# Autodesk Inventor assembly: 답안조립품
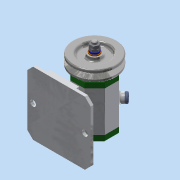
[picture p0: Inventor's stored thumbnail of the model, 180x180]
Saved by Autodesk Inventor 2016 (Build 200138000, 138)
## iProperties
Created: 2018-06
Part Number: 답안조립품
Material: 일반
Document SubType Name: Assembly
Designer: 605-07
Author: 605-07
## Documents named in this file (16)
- C:\Users\605-07\Desktop\480608V1002\답안조립품.iam
- C:\Users\605-07\Desktop\480608V1002\V벨트풀리.ipt
- C:\Users\605-07\Desktop\480608V1002\고무캡.ipt
- C:\Users\605-07\Desktop\480608V1002\너트 M8.ipt
- 너트 M8.ipt
- C:\Users\605-07\Desktop\480608V1002\뒤커버.ipt
- C:\Users\605-07\Desktop\480608V1002\베어링 15x32x9.ipt
- C:\Users\605-07\Desktop\480608V1002\본체.ipt
- C:\Users\605-07\Desktop\480608V1002\볼트 M4x12.ipt
- C:\Users\605-07\Desktop\480608V1002\스프링와셔 8.ipt
- C:\Users\605-07\Desktop\480608V1002\앞커버.ipt
- C:\Users\605-07\Desktop\480608V1002\오일 실 15 25 7.ipt
- C:\Users\605-07\Desktop\480608V1002\와셔 8x17.ipt
- C:\Users\605-07\Desktop\480608V1002\축.ipt
- C:\Users\605-07\Desktop\480608V1002\키 3x3x12.ipt
- 키 3x3x12.ipt
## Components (2 placed, 2 different names)
1. V벨트풀리:1 — 각도:1
2. 고무캡:1
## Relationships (1: Angle 1)
- 각도:1 [Angle]: V벨트풀리:1
